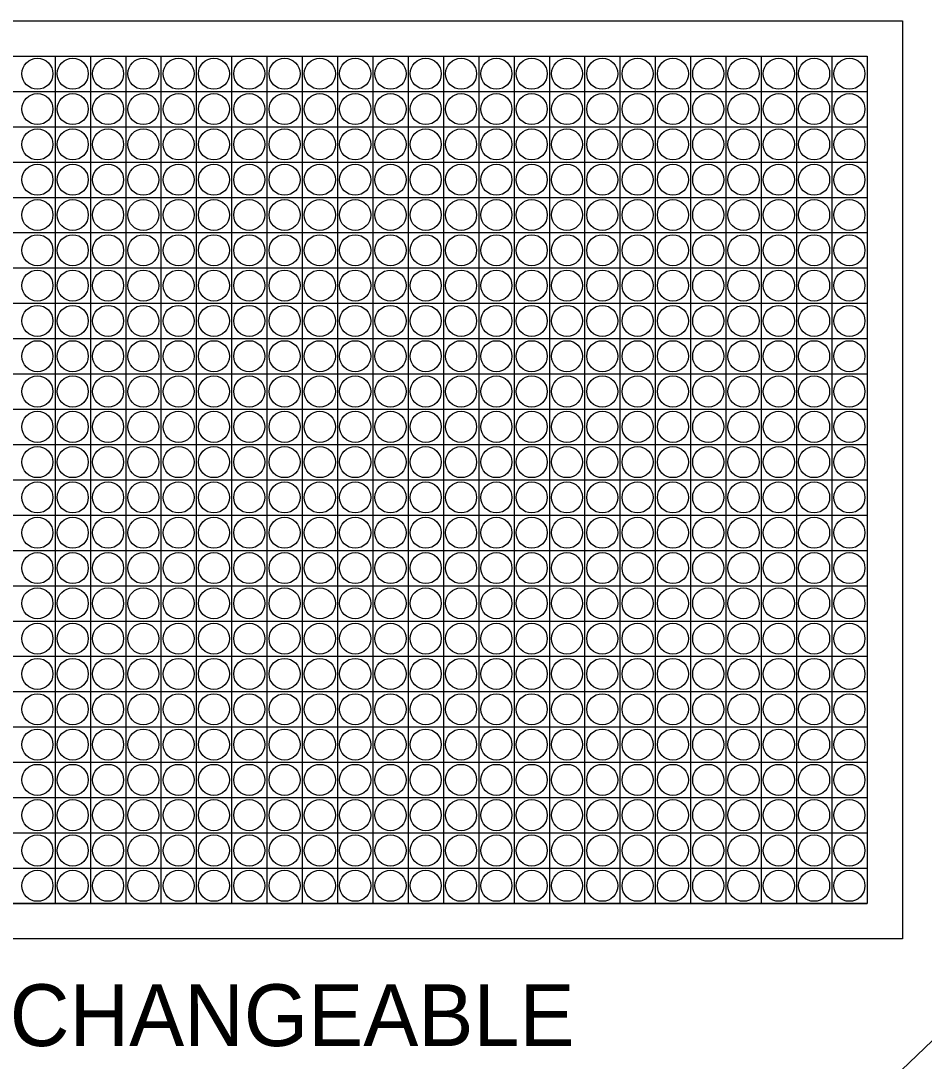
# Model space of a CAD drawing. Extents: x 15261 to 18126, y 1908 to 6555.
# Drawn here: x 16378.4 to 16480.8, y 2534 to 2651.9 of the extents above; entities that cross this region are included whole.
import ezdxf

# ---------------------------------------------------------------- set-up
doc = ezdxf.new("R2010")
doc.units = 0
for name, color, linetype in [('TRAFFIC_SIGNS_PR', 7, 'Continuous'), ('TYPICAL_TEXT_DIMEN_EX', 7, 'Continuous'), ('TYPICAL_TEXT_DIMEN_PR', 7, 'Continuous')]:
    doc.layers.add(name, color=color, linetype=linetype)

msp = doc.modelspace()

# ---------------------------------------------------------------- linework, layer by layer
at = {"layer": 'TRAFFIC_SIGNS_PR'}
for p, q in [((16382.29, 2647.89), (16382.29, 2551.89)), ((16386.29, 2647.89), (16386.29, 2551.89)), ((16390.29, 2647.89), (16390.29, 2551.89)), ((16394.29, 2647.89), (16394.29, 2551.89)), ((16398.29, 2647.89), (16398.29, 2551.89)), ((16402.29, 2647.89), (16402.29, 2551.89)), ((16406.29, 2647.89), (16406.29, 2551.89)), ((16410.29, 2647.89), (16410.29, 2551.89)), ((16414.29, 2647.89), (16414.29, 2551.89)), ((16418.29, 2647.89), (16418.29, 2551.89)), ((16422.29, 2647.89), (16422.29, 2551.89)), ((16426.29, 2647.89), (16426.29, 2551.89)), ((16430.29, 2647.89), (16430.29, 2551.89)), ((16434.29, 2647.89), (16434.29, 2551.89)), ((16438.29, 2647.89), (16438.29, 2551.89)), ((16442.29, 2647.89), (16442.29, 2551.89)), ((16446.29, 2647.89), (16446.29, 2551.89)), ((16450.29, 2647.89), (16450.29, 2551.89)), ((16454.29, 2647.89), (16454.29, 2551.89)), ((16458.29, 2647.89), (16458.29, 2551.89)), ((16462.29, 2647.89), (16462.29, 2551.89)), ((16466.29, 2647.89), (16466.29, 2551.89)), ((16470.29, 2647.89), (16470.29, 2551.89)), ((16282.29, 2643.89), (16474.29, 2643.89)), ((16282.29, 2639.89), (16474.29, 2639.89)), ((16282.29, 2635.89), (16474.29, 2635.89)), ((16282.29, 2631.89), (16474.29, 2631.89)), ((16282.29, 2627.89), (16474.29, 2627.89)), ((16282.29, 2623.89), (16474.29, 2623.89)), ((16282.29, 2619.89), (16474.29, 2619.89)), ((16282.29, 2615.89), (16474.29, 2615.89)), ((16282.29, 2611.89), (16474.29, 2611.89)), ((16282.29, 2607.89), (16474.29, 2607.89)), ((16282.29, 2603.89), (16474.29, 2603.89)), ((16282.29, 2599.89), (16474.29, 2599.89)), ((16282.29, 2595.89), (16474.29, 2595.89)), ((16282.29, 2591.89), (16474.29, 2591.89)), ((16282.29, 2587.89), (16474.29, 2587.89)), ((16282.29, 2583.89), (16474.29, 2583.89)), ((16282.29, 2579.89), (16474.29, 2579.89)), ((16282.29, 2575.89), (16474.29, 2575.89)), ((16282.29, 2571.89), (16474.29, 2571.89)), ((16282.29, 2567.89), (16474.29, 2567.89)), ((16282.29, 2563.89), (16474.29, 2563.89)), ((16282.29, 2559.89), (16474.29, 2559.89)), ((16282.29, 2555.89), (16474.29, 2555.89)), ((16282.29, 2551.89), (16474.29, 2551.89))]:
    msp.add_line(p, q, dxfattribs=at)
for points in [[(16278.29, 2651.89), (16478.29, 2651.89), (16478.29, 2547.89), (16278.29, 2547.89)], [(16282.29, 2647.89), (16474.29, 2647.89), (16474.29, 2551.89), (16282.29, 2551.89)]]:
    msp.add_lwpolyline(points, close=True, dxfattribs=at)
at = {"layer": 'TYPICAL_TEXT_DIMEN_EX'}
for centre in [(16380.29, 2645.89), (16384.29, 2645.89), (16388.29, 2645.89), (16392.29, 2645.89), (16396.29, 2645.89), (16400.29, 2645.89), (16404.29, 2645.89), (16408.29, 2645.89), (16412.29, 2645.89), (16416.29, 2645.89), (16420.29, 2645.89), (16424.29, 2645.89), (16428.29, 2645.89), (16432.29, 2645.89), (16436.29, 2645.89), (16440.29, 2645.89), (16444.29, 2645.89), (16448.29, 2645.89), (16452.29, 2645.89), (16456.29, 2645.89), (16460.29, 2645.89), (16464.29, 2645.89), (16468.29, 2645.89), (16472.29, 2645.89), (16380.29, 2641.89), (16384.29, 2641.89), (16388.29, 2641.89), (16392.29, 2641.89), (16396.29, 2641.89), (16400.29, 2641.89), (16404.29, 2641.89), (16408.29, 2641.89), (16412.29, 2641.89), (16416.29, 2641.89), (16420.29, 2641.89), (16424.29, 2641.89), (16428.29, 2641.89), (16432.29, 2641.89), (16436.29, 2641.89), (16440.29, 2641.89), (16444.29, 2641.89), (16448.29, 2641.89), (16452.29, 2641.89), (16456.29, 2641.89), (16460.29, 2641.89), (16464.29, 2641.89), (16468.29, 2641.89), (16472.29, 2641.89), (16380.29, 2637.89), (16384.29, 2637.89), (16388.29, 2637.89), (16392.29, 2637.89), (16396.29, 2637.89), (16400.29, 2637.89), (16404.29, 2637.89), (16408.29, 2637.89), (16412.29, 2637.89), (16416.29, 2637.89), (16420.29, 2637.89), (16424.29, 2637.89), (16428.29, 2637.89), (16432.29, 2637.89), (16436.29, 2637.89), (16440.29, 2637.89), (16444.29, 2637.89), (16448.29, 2637.89), (16452.29, 2637.89), (16456.29, 2637.89), (16460.29, 2637.89), (16464.29, 2637.89), (16468.29, 2637.89), (16472.29, 2637.89), (16380.29, 2633.89), (16384.29, 2633.89), (16388.29, 2633.89), (16392.29, 2633.89), (16396.29, 2633.89), (16400.29, 2633.89), (16404.29, 2633.89), (16408.29, 2633.89), (16412.29, 2633.89), (16416.29, 2633.89), (16420.29, 2633.89), (16424.29, 2633.89), (16428.29, 2633.89), (16432.29, 2633.89), (16436.29, 2633.89), (16440.29, 2633.89), (16444.29, 2633.89), (16448.29, 2633.89), (16452.29, 2633.89), (16456.29, 2633.89), (16460.29, 2633.89), (16464.29, 2633.89), (16468.29, 2633.89), (16472.29, 2633.89), (16380.29, 2629.89), (16384.29, 2629.89), (16388.29, 2629.89), (16392.29, 2629.89), (16396.29, 2629.89), (16400.29, 2629.89), (16404.29, 2629.89), (16408.29, 2629.89), (16412.29, 2629.89), (16416.29, 2629.89), (16420.29, 2629.89), (16424.29, 2629.89), (16428.29, 2629.89), (16432.29, 2629.89), (16436.29, 2629.89), (16440.29, 2629.89), (16444.29, 2629.89), (16448.29, 2629.89), (16452.29, 2629.89), (16456.29, 2629.89), (16460.29, 2629.89), (16464.29, 2629.89), (16468.29, 2629.89), (16472.29, 2629.89), (16380.29, 2625.89), (16384.29, 2625.89), (16388.29, 2625.89), (16392.29, 2625.89), (16396.29, 2625.89), (16400.29, 2625.89), (16404.29, 2625.89), (16408.29, 2625.89), (16412.29, 2625.89), (16416.29, 2625.89), (16420.29, 2625.89), (16424.29, 2625.89), (16428.29, 2625.89), (16432.29, 2625.89), (16436.29, 2625.89), (16440.29, 2625.89), (16444.29, 2625.89), (16448.29, 2625.89), (16452.29, 2625.89), (16456.29, 2625.89), (16460.29, 2625.89), (16464.29, 2625.89), (16468.29, 2625.89), (16472.29, 2625.89), (16380.29, 2621.89), (16384.29, 2621.89), (16388.29, 2621.89), (16392.29, 2621.89), (16396.29, 2621.89), (16400.29, 2621.89), (16404.29, 2621.89), (16408.29, 2621.89), (16412.29, 2621.89), (16416.29, 2621.89), (16420.29, 2621.89), (16424.29, 2621.89), (16428.29, 2621.89), (16432.29, 2621.89), (16436.29, 2621.89), (16440.29, 2621.89), (16444.29, 2621.89), (16448.29, 2621.89), (16452.29, 2621.89), (16456.29, 2621.89), (16460.29, 2621.89), (16464.29, 2621.89), (16468.29, 2621.89), (16472.29, 2621.89), (16380.29, 2617.89), (16384.29, 2617.89), (16388.29, 2617.89), (16392.29, 2617.89), (16396.29, 2617.89), (16400.29, 2617.89), (16404.29, 2617.89), (16408.29, 2617.89), (16412.29, 2617.89), (16416.29, 2617.89), (16420.29, 2617.89), (16424.29, 2617.89), (16428.29, 2617.89), (16432.29, 2617.89), (16436.29, 2617.89), (16440.29, 2617.89), (16444.29, 2617.89), (16448.29, 2617.89), (16452.29, 2617.89), (16456.29, 2617.89), (16460.29, 2617.89), (16464.29, 2617.89), (16468.29, 2617.89), (16472.29, 2617.89), (16380.29, 2613.89), (16384.29, 2613.89), (16388.29, 2613.89), (16392.29, 2613.89), (16396.29, 2613.89), (16400.29, 2613.89), (16404.29, 2613.89), (16408.29, 2613.89), (16412.29, 2613.89), (16416.29, 2613.89), (16420.29, 2613.89), (16424.29, 2613.89), (16428.29, 2613.89), (16432.29, 2613.89), (16436.29, 2613.89), (16440.29, 2613.89), (16444.29, 2613.89), (16448.29, 2613.89), (16452.29, 2613.89), (16456.29, 2613.89), (16460.29, 2613.89), (16464.29, 2613.89), (16468.29, 2613.89), (16472.29, 2613.89), (16380.29, 2609.89), (16384.29, 2609.89), (16388.29, 2609.89), (16392.29, 2609.89), (16396.29, 2609.89), (16400.29, 2609.89), (16404.29, 2609.89), (16408.29, 2609.89), (16412.29, 2609.89), (16416.29, 2609.89), (16420.29, 2609.89), (16424.29, 2609.89), (16428.29, 2609.89), (16432.29, 2609.89), (16436.29, 2609.89), (16440.29, 2609.89), (16444.29, 2609.89), (16448.29, 2609.89), (16452.29, 2609.89), (16456.29, 2609.89), (16460.29, 2609.89), (16464.29, 2609.89), (16468.29, 2609.89), (16472.29, 2609.89), (16380.29, 2605.89), (16384.29, 2605.89), (16388.29, 2605.89), (16392.29, 2605.89), (16396.29, 2605.89), (16400.29, 2605.89), (16404.29, 2605.89), (16408.29, 2605.89), (16412.29, 2605.89), (16416.29, 2605.89), (16420.29, 2605.89), (16424.29, 2605.89), (16428.29, 2605.89), (16432.29, 2605.89), (16436.29, 2605.89), (16440.29, 2605.89), (16444.29, 2605.89), (16448.29, 2605.89), (16452.29, 2605.89), (16456.29, 2605.89), (16460.29, 2605.89), (16464.29, 2605.89), (16468.29, 2605.89), (16472.29, 2605.89), (16380.29, 2601.89), (16384.29, 2601.89), (16388.29, 2601.89), (16392.29, 2601.89), (16396.29, 2601.89), (16400.29, 2601.89), (16404.29, 2601.89), (16408.29, 2601.89), (16412.29, 2601.89), (16416.29, 2601.89), (16420.29, 2601.89), (16424.29, 2601.89), (16428.29, 2601.89), (16432.29, 2601.89), (16436.29, 2601.89), (16440.29, 2601.89), (16444.29, 2601.89), (16448.29, 2601.89), (16452.29, 2601.89), (16456.29, 2601.89), (16460.29, 2601.89), (16464.29, 2601.89), (16468.29, 2601.89), (16472.29, 2601.89), (16380.29, 2597.89), (16384.29, 2597.89), (16388.29, 2597.89), (16392.29, 2597.89), (16396.29, 2597.89), (16400.29, 2597.89), (16404.29, 2597.89), (16408.29, 2597.89), (16412.29, 2597.89), (16416.29, 2597.89), (16420.29, 2597.89), (16424.29, 2597.89), (16428.29, 2597.89), (16432.29, 2597.89), (16436.29, 2597.89), (16440.29, 2597.89), (16444.29, 2597.89), (16448.29, 2597.89), (16452.29, 2597.89), (16456.29, 2597.89), (16460.29, 2597.89), (16464.29, 2597.89), (16468.29, 2597.89), (16472.29, 2597.89), (16380.29, 2593.89), (16384.29, 2593.89), (16388.29, 2593.89), (16392.29, 2593.89), (16396.29, 2593.89), (16400.29, 2593.89), (16404.29, 2593.89), (16408.29, 2593.89), (16412.29, 2593.89), (16416.29, 2593.89), (16420.29, 2593.89), (16424.29, 2593.89), (16428.29, 2593.89), (16432.29, 2593.89), (16436.29, 2593.89), (16440.29, 2593.89), (16444.29, 2593.89), (16448.29, 2593.89), (16452.29, 2593.89), (16456.29, 2593.89), (16460.29, 2593.89), (16464.29, 2593.89), (16468.29, 2593.89), (16472.29, 2593.89), (16380.29, 2589.89), (16384.29, 2589.89), (16388.29, 2589.89), (16392.29, 2589.89), (16396.29, 2589.89), (16400.29, 2589.89), (16404.29, 2589.89), (16408.29, 2589.89), (16412.29, 2589.89), (16416.29, 2589.89), (16420.29, 2589.89), (16424.29, 2589.89), (16428.29, 2589.89), (16432.29, 2589.89), (16436.29, 2589.89), (16440.29, 2589.89), (16444.29, 2589.89), (16448.29, 2589.89), (16452.29, 2589.89), (16456.29, 2589.89), (16460.29, 2589.89), (16464.29, 2589.89), (16468.29, 2589.89), (16472.29, 2589.89), (16380.29, 2585.89), (16384.29, 2585.89), (16388.29, 2585.89), (16392.29, 2585.89), (16396.29, 2585.89), (16400.29, 2585.89), (16404.29, 2585.89), (16408.29, 2585.89), (16412.29, 2585.89), (16416.29, 2585.89), (16420.29, 2585.89), (16424.29, 2585.89), (16428.29, 2585.89), (16432.29, 2585.89), (16436.29, 2585.89), (16440.29, 2585.89), (16444.29, 2585.89), (16448.29, 2585.89), (16452.29, 2585.89), (16456.29, 2585.89), (16460.29, 2585.89), (16464.29, 2585.89), (16468.29, 2585.89), (16472.29, 2585.89), (16380.29, 2581.89), (16384.29, 2581.89), (16388.29, 2581.89), (16392.29, 2581.89), (16396.29, 2581.89), (16400.29, 2581.89), (16404.29, 2581.89), (16408.29, 2581.89), (16412.29, 2581.89), (16416.29, 2581.89), (16420.29, 2581.89), (16424.29, 2581.89), (16428.29, 2581.89), (16432.29, 2581.89), (16436.29, 2581.89), (16440.29, 2581.89), (16444.29, 2581.89), (16448.29, 2581.89), (16452.29, 2581.89), (16456.29, 2581.89), (16460.29, 2581.89), (16464.29, 2581.89), (16468.29, 2581.89), (16472.29, 2581.89), (16380.29, 2577.89), (16384.29, 2577.89), (16388.29, 2577.89), (16392.29, 2577.89), (16396.29, 2577.89), (16400.29, 2577.89), (16404.29, 2577.89), (16408.29, 2577.89), (16412.29, 2577.89), (16416.29, 2577.89), (16420.29, 2577.89), (16424.29, 2577.89), (16428.29, 2577.89), (16432.29, 2577.89), (16436.29, 2577.89), (16440.29, 2577.89), (16444.29, 2577.89), (16448.29, 2577.89), (16452.29, 2577.89), (16456.29, 2577.89), (16460.29, 2577.89), (16464.29, 2577.89), (16468.29, 2577.89), (16472.29, 2577.89), (16380.29, 2573.89), (16384.29, 2573.89), (16388.29, 2573.89), (16392.29, 2573.89), (16396.29, 2573.89), (16400.29, 2573.89), (16404.29, 2573.89), (16408.29, 2573.89), (16412.29, 2573.89), (16416.29, 2573.89), (16420.29, 2573.89), (16424.29, 2573.89), (16428.29, 2573.89), (16432.29, 2573.89), (16436.29, 2573.89), (16440.29, 2573.89), (16444.29, 2573.89), (16448.29, 2573.89), (16452.29, 2573.89), (16456.29, 2573.89), (16460.29, 2573.89), (16464.29, 2573.89), (16468.29, 2573.89), (16472.29, 2573.89), (16380.29, 2569.89), (16384.29, 2569.89), (16388.29, 2569.89), (16392.29, 2569.89), (16396.29, 2569.89), (16400.29, 2569.89), (16404.29, 2569.89), (16408.29, 2569.89), (16412.29, 2569.89), (16416.29, 2569.89), (16420.29, 2569.89), (16424.29, 2569.89), (16428.29, 2569.89), (16432.29, 2569.89), (16436.29, 2569.89), (16440.29, 2569.89), (16444.29, 2569.89), (16448.29, 2569.89), (16452.29, 2569.89), (16456.29, 2569.89), (16460.29, 2569.89), (16464.29, 2569.89), (16468.29, 2569.89), (16472.29, 2569.89), (16380.29, 2565.89), (16384.29, 2565.89), (16388.29, 2565.89), (16392.29, 2565.89), (16396.29, 2565.89), (16400.29, 2565.89), (16404.29, 2565.89), (16408.29, 2565.89), (16412.29, 2565.89), (16416.29, 2565.89), (16420.29, 2565.89), (16424.29, 2565.89), (16428.29, 2565.89), (16432.29, 2565.89), (16436.29, 2565.89), (16440.29, 2565.89), (16444.29, 2565.89), (16448.29, 2565.89), (16452.29, 2565.89), (16456.29, 2565.89), (16460.29, 2565.89), (16464.29, 2565.89), (16468.29, 2565.89), (16472.29, 2565.89), (16380.29, 2561.89), (16384.29, 2561.89), (16388.29, 2561.89), (16392.29, 2561.89), (16396.29, 2561.89), (16400.29, 2561.89), (16404.29, 2561.89), (16408.29, 2561.89), (16412.29, 2561.89), (16416.29, 2561.89), (16420.29, 2561.89), (16424.29, 2561.89), (16428.29, 2561.89), (16432.29, 2561.89), (16436.29, 2561.89), (16440.29, 2561.89), (16444.29, 2561.89), (16448.29, 2561.89), (16452.29, 2561.89), (16456.29, 2561.89), (16460.29, 2561.89), (16464.29, 2561.89), (16468.29, 2561.89), (16472.29, 2561.89), (16380.29, 2557.89), (16384.29, 2557.89), (16388.29, 2557.89), (16392.29, 2557.89), (16396.29, 2557.89), (16400.29, 2557.89), (16404.29, 2557.89), (16408.29, 2557.89), (16412.29, 2557.89), (16416.29, 2557.89), (16420.29, 2557.89), (16424.29, 2557.89), (16428.29, 2557.89), (16432.29, 2557.89), (16436.29, 2557.89), (16440.29, 2557.89), (16444.29, 2557.89), (16448.29, 2557.89), (16452.29, 2557.89), (16456.29, 2557.89), (16460.29, 2557.89), (16464.29, 2557.89), (16468.29, 2557.89), (16472.29, 2557.89), (16380.29, 2553.89), (16384.29, 2553.89), (16388.29, 2553.89), (16392.29, 2553.89), (16396.29, 2553.89), (16400.29, 2553.89), (16404.29, 2553.89), (16408.29, 2553.89), (16412.29, 2553.89), (16416.29, 2553.89), (16420.29, 2553.89), (16424.29, 2553.89), (16428.29, 2553.89), (16432.29, 2553.89), (16436.29, 2553.89), (16440.29, 2553.89), (16444.29, 2553.89), (16448.29, 2553.89), (16452.29, 2553.89), (16456.29, 2553.89), (16460.29, 2553.89), (16464.29, 2553.89), (16468.29, 2553.89), (16472.29, 2553.89)]:
    msp.add_circle(centre, 1.76, dxfattribs=at)
at = {"layer": 'TYPICAL_TEXT_DIMEN_PR'}
msp.add_line((16494.38, 2548.48), (16432.89, 2489.71), dxfattribs=at)

# ---------------------------------------------------------------- texts
at = {"layer": 'TRAFFIC_SIGNS_PR'}
msp.add_text('PORTABLE CHANGEABLE', height=7, dxfattribs=at).set_placement((16324.62, 2535.73))

doc.saveas('drawing.dxf')
